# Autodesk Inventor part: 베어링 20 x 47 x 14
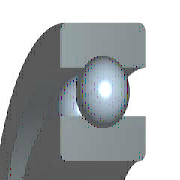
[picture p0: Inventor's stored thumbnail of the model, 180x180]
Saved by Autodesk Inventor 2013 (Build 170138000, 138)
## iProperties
IsCustomPart: 1
Created: 2012-02
Part Number: 베어링 20 x 47 x 14
Material: 강철, 연강
Description: 깊은 그루브 볼 베어링
Document SubType Name: Modeling
Standard: KS B 2023
Designer: mduedu
Standards Organization: KS
Language: ko-KR
Size Designation: 6204 - 20 x 47 x 14
Categories: <MemberInstance><Categories><Category DisplayName="샤프트 부품" InternalName="7f7aeb1f-a693-4053-b835-cee3144e0d98" Mnemonic="SHFT"><Category DisplayName="베어링" Inter
Density: 1 g/cm^3
Author: mduedu
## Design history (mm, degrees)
sketch "스케치" dims "d0" = 7.02 (= -0.26 x WD + 0.26 x BD)
  geometry: L1 (3.49, 16.75)-(10.51, 16.75); L2 (7, 16.75)-(7, 13.24); L3 (7, 16.75)-(7, 20.26); L4 (4.392, 14.401)-(0, 14.401); L5 (0, 10)-(14, 10); L6 (4.392, 19.099)-(0, 19.099); L7 (0, 23.5)-(14, 23.5); L8 (14, 10)-(14, 14.401); L9 (9.608, 14.401)-(14, 14.401); L10 (9.608, 19.099)-(14, 19.099); L11 (14, 23.5)-(14, 19.099); L12 (-1.4, 0)-(8.4, 0) reference; L13 (0, -0.3)-(0, 5.3) reference
  constraints: 22 end point, 4 point on line, 2 collinear, 2 perpendicular, 2 symmetric about line, 1 midpoint, 1 parallel, 14 other
  dimensions: "d9" = 20 diameter of L5 L12 (= WD); "d11" = 47 diameter of L7 L12 (= BD); "d12" = 14 distance between parallel lines of L8 L13 (= KB); "d13" = 28.802 diameter of L9 L12 (= 0.326 x BD + 0.674 x WD)
revolve "본체" stored, may be unused: angle "d6" = 90 deg
revolve "볼" stored, may be unused: angle "d7" = 90 deg
pattern_circular "IDS_ARRAYBALL[SIMPL:T]" dims angle "d3" = 360 deg
body "Solid1"
fillet "모깎기1" dims "d1" = 1 (= KRS)
other parameters: "WD" = 20 [user parameter; used in 5 equation terms], "BD" = 47 [user parameter; used in 5 equation terms], "KB" = 14 [user parameter; used in 1 equation term], "KRS" = 1 [user parameter; used in 1 equation term], "d4" = 0, "d5" = 0, "d8" = 0, "d14" = 0, "d15" = 0, "BBA" = 0 [user parameter], "BC0" = 6550000 [user parameter], "BC" = 1.27e+07 [user parameter], "BR" = 23.5 (= 0.5 x BD) [user parameter]
